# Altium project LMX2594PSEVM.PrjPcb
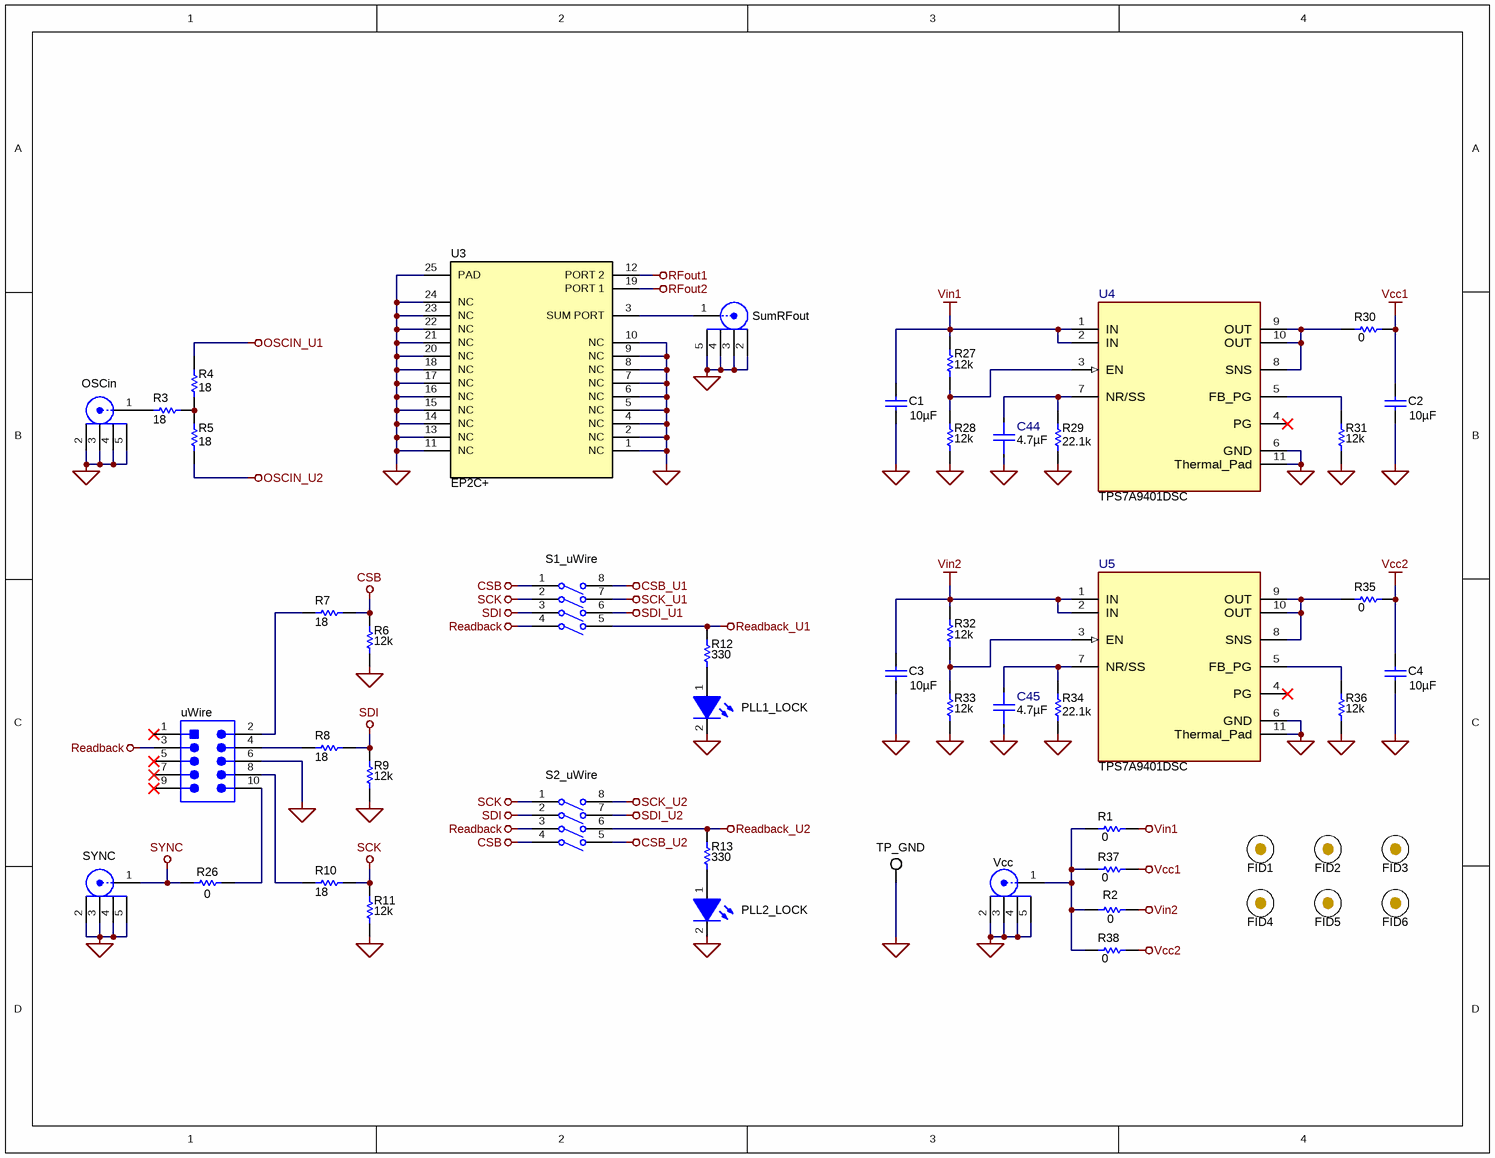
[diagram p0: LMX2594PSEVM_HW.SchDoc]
CopyrightYear: 2022; PCB_Layout: Dean Banerjee; PCB_Rev: A; PRJ_Customer: Public Release; PRJ_Engineer: Dean Banerjee; PRJ_Number: DC193; PRJ_Title: LMX2594 Phase Sync EVM; SCH_Rev: A; TechSupport: http://www.ti.com/support; TID: N/A
3 sheets, 123 parts. Net scope: global (net labels, ports and power ports of the same name join across sheets).
Board file: LMX2594PSEVM.PcbDoc
Sheets:
  LMX2594PSEVM_HW.SchDoc
  LMX2594PSEVM_SYNTH1.SchDoc
  LMX2594PSEVM_SYNTH2.SchDoc

## Sheet LMX2594PSEVM_HW.SchDoc: Power supply and control interface
size Letter; Date: Not shown in title block; ApprovedBy: Not shown in title block; CheckedBy: Not shown in title block; Author: Not shown in title block; CompanyName: Not shown in title block; DrawnBy: Dean Banerjee; Engineer: Not shown in title block; Organization: Not shown in title block; Address1: Not shown in title block; Address2: Not shown in title block; Address3: Not shown in title block; Address4: Not shown in title block; DocumentNumber: 3; Revision: Use project parameter SCH_Rev; SheetNumber: 3; SheetTotal: 4; PageSetup: Record=PageOptions¦CenterHorizontal=True¦CenterVertical=True¦PrintScale=1.00¦XCorrection=1.00¦YCorrection=1.00¦PrintKind=0¦BorderSize=5000000¦LeftOffset=0¦BottomOffset=0¦Orientation=2¦PaperLength=1000¦PaperWidth=1000¦Scale=100¦PaperSource=15¦PrintQuality=600¦MediaType=1¦DitherType=10¦PaperKind=Letter¦PrintScaleMode=1

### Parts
C1  Cap_F: 10µF  [0805]  (hidden comment: EMK212BB7106KG-T)
C2  Cap_F: 10µF  [0805]  (hidden comment: EMK212BB7106KG-T)
C3  Cap_F: 10µF  [0805]  (hidden comment: EMK212BB7106KG-T)
C4  Cap_F: 10µF  [0805]  (hidden comment: EMK212BB7106KG-T)
C44  Cap_F: 4.7µF  [FP-CGA4J1X7R1H475K125AC_0805-MFG]  (hidden comment: CGA4J1X7R1H475K125AC)
C45  Cap_F: 4.7µF  [FP-CGA4J1X7R1H475K125AC_0805-MFG]  (hidden comment: CGA4J1X7R1H475K125AC)
D1  PLL1_LOCK  [LED_LTST-C190]
D2  PLL2_LOCK  [LED_LTST-C190]
FID1  Fiducial  [Fiducial10-20]  (value not drawn)
FID2  Fiducial  [Fiducial10-20]  (value not drawn)
FID3  Fiducial  [Fiducial10-20]  (value not drawn)
FID4  Fiducial  [Fiducial10-20]  (value not drawn)
FID5  Fiducial  [Fiducial10-20]  (value not drawn)
FID6  Fiducial  [Fiducial10-20]  (value not drawn)
J3  OSCin  [Emerson_142-0701-851]
J4  SumRFout  [Johnson_142-0761-881]
J5  SYNC  [Emerson_142-0701-851]
J6  Vcc  [Emerson_142-0701-851]
R1  value 0  [0603]  (hidden comment: Resistor)
R2  value 0  [0603]  (hidden comment: Resistor)
R3  ValueDisplayed: 18  [0603]  (hidden comment: Resistor)
R4  ValueDisplayed: 18  [0603]  (hidden comment: Resistor)
R5  ValueDisplayed: 18  [0603]  (hidden comment: Resistor)
R6  value 12k  [0603]  (hidden comment: Resistor)
R7  ValueDisplayed: 18  [0603]  (hidden comment: CRCW060318R0JNEA)
R8  ValueDisplayed: 18  [0603]  (hidden comment: CRCW060318R0JNEA)
R9  value 12k  [0603]  (hidden comment: Resistor)
R10  ValueDisplayed: 18  [0603]  (hidden comment: CRCW060318R0JNEA)
R11  value 12k  [0603]  (hidden comment: Resistor)
R12  value 330  [0603]  (hidden comment: Resistor)
R13  value 330  [0603]  (hidden comment: Resistor)
R26  value 0  [0603]  (hidden comment: Resistor)
R27  value 12k  [0603]  (hidden comment: Resistor)
R28  value 12k  [0603]  (hidden comment: Resistor)
R29  ValueDisplayed: 22.1k  [0603]  (hidden comment: CRCW060322K1FKEA)
R30  value 0  [0603]  (hidden comment: Resistor)
R31  value 12k  [0603]  (hidden comment: Resistor)
R32  value 12k  [0603]  (hidden comment: Resistor)
R33  value 12k  [0603]  (hidden comment: Resistor)
R34  ValueDisplayed: 22.1k  [0603]  (hidden comment: CRCW060322K1FKEA)
R35  value 0  [0603]  (hidden comment: Resistor)
R36  value 12k  [0603]  (hidden comment: Resistor)
R37  value 0  [0603]  (hidden comment: Resistor)
R38  value 0  [0603]  (hidden comment: Resistor)
S1  S1_uWire  [SW_219-4MST]
S2  S2_uWire  [SW_219-4MST]
TP1  TP_GND  [Keystone5007]
U3  EP2C+  [DG1847]
U4  TPS7A9401DSC  [DSC0010J-MFG]
U5  TPS7A9401DSC  [DSC0010J-MFG]
uWire  Header_5x2  [FCI_52601-S10-8LF]  (value not drawn)

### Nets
CSB: R6.2 R7.2 S1.1(A1) S2.4(A4)
CSB_U1: S1.8(B1)
CSB_U2: S2.5(B4)
GND: C1.1 C2.1 C3.1 C4.1 C44.1 C45.1 D1.2(K) D2.2(K) J3.2 J3.3 J3.4 J3.5 J4.2 J4.3 J4.4 J4.5 J5.2 J5.3 J5.4 J5.5 J6.2 J6.3 J6.4 J6.5 R6.1 R9.1 R11.1 R28.1 R29.1 R31.1 R33.1 R34.1 R36.1 TP1.1 U3.1(NC) U3.2(NC) U3.4(NC) U3.5(NC) U3.6(NC) U3.7(NC) U3.8(NC) U3.9(NC) U3.10(NC) U3.11(NC) U3.13(NC) U3.14(NC) U3.15(NC) U3.16(NC) U3.17(NC) U3.18(NC) U3.20(NC) U3.21(NC) U3.22(NC) U3.23(NC) U3.24(NC) U3.25(PAD) U4.6(GND) U4.11(Thermal_Pad) U5.6(GND) U5.11(Thermal_Pad) uWire.6
OSCIN_U1: R4.2
OSCIN_U2: R5.1
Readback: S1.4(A4) S2.3(A3) uWire.3
Readback_U1: R12.2 S1.5(B4)
Readback_U2: R13.2 S2.6(B3)
RFout1: U3.12(PORT_2)
RFout2: U3.19(PORT_1)
SCK: R10.2 R11.2 S1.2(A2) S2.1(A1)
SCK_U1: S1.7(B2)
SCK_U2: S2.8(B1)
SDI: R8.1 R9.2 S1.3(A3) S2.2(A2)
SDI_U1: S1.6(B3)
SDI_U2: S2.7(B2)
SYNC: J5.1 R26.1
Vcc1: C2.2 R30.2 R37.2
Vcc2: C4.2 R35.2 R38.2
Vin1: C1.2 R1.2 R27.2 U4.1(IN) U4.2(IN)
Vin2: C3.2 R2.2 R32.2 U5.1(IN) U5.2(IN)
NetC44_2: C44.2 R29.2 U4.7(NR/SS)
NetC45_2: C45.2 R34.2 U5.7(NR/SS)
NetD1_1: D1.1(A) R12.1
NetD2_1: D2.1(A) R13.1
NetJ3_1: J3.1 R3.1
NetJ4_1: J4.1 U3.3(SUM_PORT)
NetJ6_1: J6.1 R1.1 R2.1 R37.1 R38.1
NetR3_2: R3.2 R4.1 R5.2
NetR7_1: R7.1 uWire.2
NetR8_2: R8.2 uWire.4
NetR10_1: R10.1 uWire.8
NetR26_2: R26.2 uWire.10
NetR27_1: R27.1 R28.2 U4.3(EN)
NetR30_1: R30.1 U4.8(SNS) U4.9(OUT) U4.10(OUT)
NetR31_2: R31.2 U4.5(FB_PG)
NetR32_1: R32.1 R33.2 U5.3(EN)
NetR35_1: R35.1 U5.8(SNS) U5.9(OUT) U5.10(OUT)
NetR36_2: R36.2 U5.5(FB_PG)

Not connected (* = marked no-connect by the designer): U4 4(PG)*; U5 4(PG)*; uWire 1* 5* 7* 9*

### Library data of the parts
C1-C4 = CMP-0085283-1: CAP, CERM, 10 µF, 16 V,+/- 10%, X7R, 0805; Manufacturer: Taiyo Yuden; Polarized: N; TaMax_C: 125°C; TaMin_C: -55°C; VDC_V: 16V; Value: 10uF; U/M: EA; AEC Category: Q200; SizeArea_mm2: 2.5; SizeAreaWB_mm2: 6.75; SizeX_mm: 2; SizeY_mm: 1.25; SizeZ_mm: 1.45
C44 C45 = CMP-0090082-1: Cap Ceramic 4.7uF 50V X7R 10% Pad SMD 0805 +125°C Automotive T/R; Manufacturer: TDK Corporation; TempCo: 15%; Value: 4.7µF; Tolerance_%: 0.1%; SizeZ_mm: 1.45mm; AEC Qualified: Yes; AEC Grade: Grade 1
D1 D2 = CMP-0002827-3: LED, Green, SMD; Manufacturer: Lite-On; PartNumber: LTST-C190GKT; Vf_V: 2.1V; Io_A: 20mA; Power_TotalModule: 100mW; Value1: 0.1W
FID1-FID6 = CMP-0077181-1: Fiducial mark.  There is nothing to buy or mount.
J3 J5 J6 = CMP-0055822-3: Connector, End launch SMA, 50 ohm, SMT; PartNumber: 142-0701-851; Manufacturer: Cinch Connectivity; Green_Lifecycle: Not Set; Green_REACh: Incomplete
J4 = CMP-0055835-1: Connector, End launch SMA 50 ohm, TH; PartNumber: 142-0761-881; Manufacturer: Cinch Connectivity; CNHeader: FALSE; CT: TRUE; Green_Lifecycle: Not Set; Green_REACh: Incomplete
R1 R2 R26 R30 R35 R37 R38 = CMP-0025697-4: RES, 0, 5%, 0.1 W, AEC-Q200 Grade 0, 0603; Manufacturer: Vishay-Dale; PartNumber: CRCW06030000Z0EA; VDC_V: 75V; Power_W: 100mW; Value_Code: 0000; Value2: 0.1W; EIA_Code: E24; AEC Category: Q200; AEC Qualified: Y; SizeArea_mm2: 1.28; SizeX_mm: 1.6; SizeY_mm: 0.8; SizeZ_mm: 1; TempCo: 200 ppm/C
R3-R5 = CMP-0025728-4: RES, 18, 5%, 0.1 W, AEC-Q200 Grade 0, 0603; Manufacturer: Vishay-Dale; PartNumber: CRCW060318R0JNEA; VDC_V: 75V; Power_W: 100mW; Value: 18; Value_Code: 18R0; Value2: 0.1W; EIA_Code: E24; TempCo: 200 ppm/C; SizeArea_mm2: 1.28; SizeX_mm: 1.6; SizeY_mm: 0.8; SizeZ_mm: 1; AEC Category: Q200; AEC Qualified: Y; AEC Grade: 0
R6 R9 R11 R27 R28 R31-R33 R36 = CMP-0025711-4: RES, 12 k, 5%, 0.1 W, AEC-Q200 Grade 0, 0603; Manufacturer: Vishay-Dale; PartNumber: CRCW060312K0JNEA; VDC_V: 75V; Power_W: 100mW; Value_Code: 12k0; Value2: 0.1W; EIA_Code: E24; AEC Category: Q200; AEC Grade: 0; AEC Qualified: Y; SizeArea_mm2: 1.28; SizeX_mm: 1.6; SizeY_mm: 0.8; SizeZ_mm: 1; TempCo: 200 ppm/C
R7 R8 R10 = CMP-0025728-4: RES, 18, 5%, 0.1 W, AEC-Q200 Grade 0, 0603; Manufacturer: Vishay-Dale; VDC_V: 75V; Power_W: 100mW; Value: 18; Value_Code: 18R0; Value2: 0.1W; EIA_Code: E24; AEC Category: Q200; AEC Grade: 0; AEC Qualified: Y; SizeArea_mm2: 1.28; SizeX_mm: 1.6; SizeY_mm: 0.8; SizeZ_mm: 1; TempCo: 200 ppm/C
R12 R13 = CMP-0025912-5: RES, 330, 5%, 0.1 W, 0603; Manufacturer: Yageo; PartNumber: RC0603JR-07330RL; VDC_V: 75V; Power_W: 100mW; Value_Code: 330R; Value2: 0.1W; EIA_Code: E24; AEC Category: Q200; AEC Qualified: N; SizeArea_mm2: 1.28; SizeAreaWB_mm2: 4.68; SizeX_mm: 1.6; SizeY_mm: 0.8; SizeZ_mm: 1; TempCo: 100 ppm/C
R29 R34 = CMP-0022220-4: RES, 22.1 k, 1%, 0.1 W, AEC-Q200 Grade 0, 0603; Manufacturer: Vishay-Dale; Power_W: 100mW; TempCo: 100 ppm/C; Value_Code: 22k1; Value: 22.1k; EIA_Code: E96; SizeX_mm: 1.6; SizeY_mm: 0.8; SizeZ_mm: 1; Value2: 0.1W; SizeArea_mm2: 1.28; AEC Qualified: Y; VDC_V: 75V; AEC Category: Q200; AEC Grade: 0
S1 S2 = CMP-0002291-1: Switch, SPST, Slide, Off-On, 4 Pos, 0.1A, 20V, SMD; PartNumber: 219-4MST; Manufacturer: CTS Electrocomponents; PositionCount: 4; CurrentRating_mA: 100A; SizeArea_mm2: 115.2533; SizeAreaWB_mm2: 162.3333; SizeX_mm: 9.91; SizeY_mm: 11.63; SizeZ_mm: 4.23
TP1 = CMP-0055144-2: Test Point, Compact, White, TH; Manufacturer: Keystone Electronics; CNHeader: FALSE; ContactFinish: Silver; CT: TRUE; Green_Lifecycle: Active; Green_REACh: Passed
U3 = CMP-0065468-1: Power Splitter/Combiner, 2 Way-0°, 50Ohm, 1800 to 12500 MHz; Manufacturer: Minicircuits; SizeArea_mm2: 16.0; SizeAreaWB_mm2: 25.0; SizeX_mm: 4.0; SizeZ_mm: 1.0
U4 U5 = CMP-0091022-1: 1-A, Ultra-Low Noise, Ultra-High PSRR, RF Voltage Regulator; Manufacturer: Texas Instruments; Max Supply Voltage: 5.5V; Accuracy Percentage: 1-1.5%; SizeZ_mm: 0.8mm; Output Type: AdjustableProgrammable; Min Supply Voltage: 1.7V; TJmax_C: +150°C; Dropout Voltage: 210mV; AEC Qualified: No; Standoff Height: 0mm; Output Voltage: 0.4-5.3V; Number Of Outputs: 1; Nominal Supply Current: 15-47mA
uWire = CMP-0055434-2: Header (shrouded), 100mil, 5x2, Gold, SMT; Manufacturer: FCI; PartNumber: 52601-S10-8LF; Green_Lifecycle: Active; Green_REACh: Passed

## Sheet LMX2594PSEVM_SYNTH1.SchDoc: Synthesizer 1
size Letter; Date: Not shown in title block; ApprovedBy: Not shown in title block; CheckedBy: Not shown in title block; Author: Not shown in title block; CompanyName: Not shown in title block; Engineer: Not shown in title block; Organization: Not shown in title block; Address1: Not shown in title block; Address2: Not shown in title block; Address3: Not shown in title block; Address4: Not shown in title block; DocumentNumber: 1; Revision: Use project parameter SCH_Rev; SheetNumber: 1; SheetTotal: 4; PageSetup: Record=PageOptions¦CenterHorizontal=True¦CenterVertical=True¦PrintScale=1.00¦XCorrection=1.00¦YCorrection=1.00¦PrintKind=0¦BorderSize=5000000¦LeftOffset=0¦BottomOffset=0¦Orientation=2¦PaperLength=1000¦PaperWidth=1000¦Scale=100¦PaperSource=15¦PrintQuality=600¦MediaType=1¦DitherType=10¦PaperKind=Letter¦PrintScaleMode=1
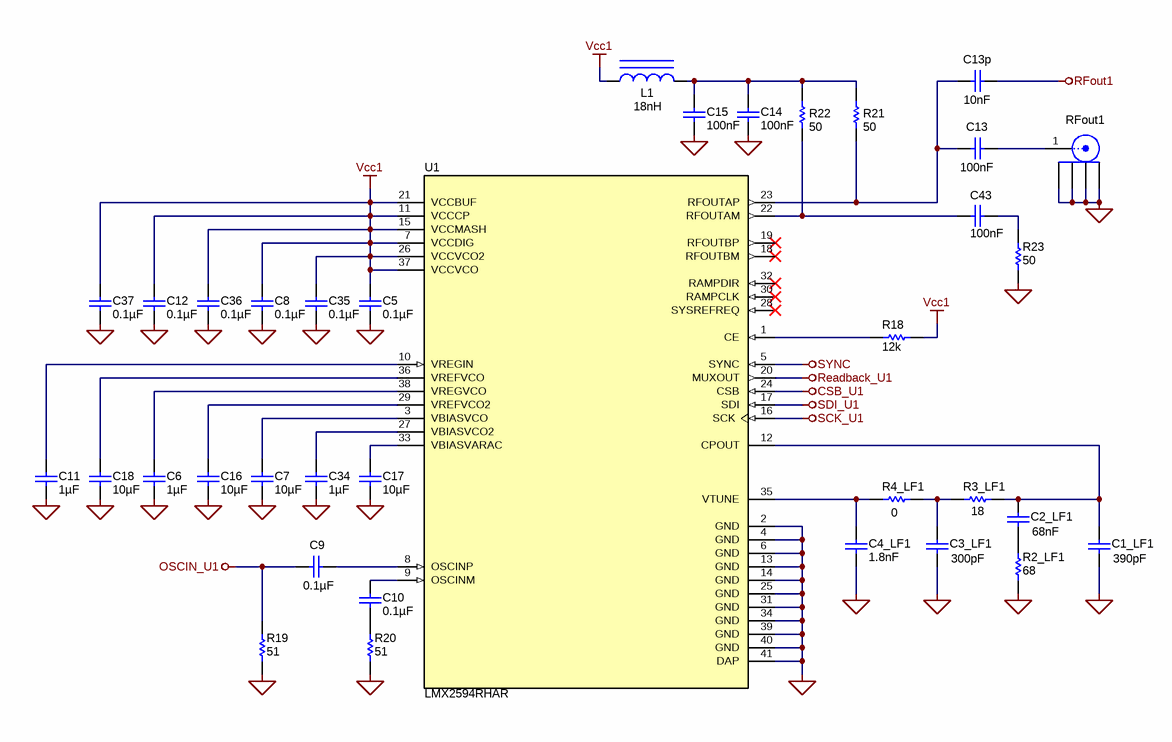
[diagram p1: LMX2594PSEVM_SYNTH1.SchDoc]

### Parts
C1_LF1  ValueDisplayed: 390pF  [0603]  (hidden comment: 06035A391JAT2A)
C2_LF1  Cap_F: 68nF  [0603]  (hidden comment: 885012206070)
C3_LF1  ValueDisplayed: 300pF  [0603]  (hidden comment: GRM1885C1H301JA01D)
C4_LF1  ValueDisplayed: 1.8nF  [0603]  (hidden comment: Capacitor)
C5  ValueDisplayed: 0.1µF  [0603]  (hidden comment: Capacitor)
C6  Cap_F: 1µF  [0603]  (hidden comment: 885012206052)
C7  ValueDisplayed: 10µF  [0603]  (hidden comment: GRM188R61A106KAALD)
C8  ValueDisplayed: 0.1µF  [0603]  (hidden comment: Capacitor)
C9  ValueDisplayed: 0.1µF  [0603]  (hidden comment: Capacitor)
C10  ValueDisplayed: 0.1µF  [0603L]  (hidden comment: Capacitor)
C11  Cap_F: 1µF  [0603]  (hidden comment: 885012206052)
C12  ValueDisplayed: 0.1µF  [0603L]  (hidden comment: Capacitor)
C13  ValueDisplayed: 100nF  [0402_065L]  (hidden comment: Capacitor)
C13p  ValueDisplayed: 10nF  [0402S]  (hidden comment: C0402C103J5RACTU)
C14  ValueDisplayed: 100nF  [0402_065L]  (hidden comment: Capacitor)
C15  ValueDisplayed: 100nF  [0402_065L]  (hidden comment: Capacitor)
C16  ValueDisplayed: 10µF  [0603]  (hidden comment: GRM188R61A106KAALD)
C17  ValueDisplayed: 10µF  [0603]  (hidden comment: GRM188R61A106KAALD)
C18  ValueDisplayed: 10µF  [0603]  (hidden comment: GRM188R61A106KAALD)
C34  Cap_F: 1µF  [0603]  (hidden comment: 885012206052)
C35  ValueDisplayed: 0.1µF  [0603L]  (hidden comment: Capacitor)
C36  ValueDisplayed: 0.1µF  [0603]  (hidden comment: Capacitor)
C37  ValueDisplayed: 0.1µF  [0603L]  (hidden comment: Capacitor)
C43  ValueDisplayed: 100nF  [0402_065L]  (hidden comment: Capacitor)
J1  RFout1  [Johnson_142-0761-881]
L1  ValueDisplayed: 18nH  [IND_LQG15H]  (hidden comment: Inductor_Iron)
R2_LF1  ValueDisplayed: 68  [0603]  (hidden comment: Resistor)
R3_LF1  ValueDisplayed: 18  [0603]  (hidden comment: Resistor)
R4_LF1  value 0  [0603]  (hidden comment: Resistor)
R18  value 12k  [0603]  (hidden comment: Resistor)
R19  ValueDisplayed: 51  [0603]  (hidden comment: Resistor)
R20  ValueDisplayed: 51  [0603]  (hidden comment: Resistor)
R21  ValueDisplayed: 50  [0402L]  (hidden comment: Resistor)
R22  ValueDisplayed: 50  [0402L]  (hidden comment: Resistor)
R23  ValueDisplayed: 50  [0402]  (hidden comment: Resistor)
U1  LMX2594RHAR  [RHA0040H]

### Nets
CSB_U1: U1.24(CSB)
GND: C1_LF1.2 C3_LF1.2 C4_LF1.2 C5.2 C6.2 C7.2 C8.1 C11.1 C12.1 C14.1 C15.1 C16.2 C17.2 C18.2 C34.1 C35.2 C36.1 C37.2 J1.2 J1.3 J1.4 J1.5 R2_LF1.2 R19.1 R20.1 R23.2 U1.2(GND) U1.4(GND) U1.6(GND) U1.13(GND) U1.14(GND) U1.25(GND) U1.31(GND) U1.34(GND) U1.39(GND) U1.40(GND) U1.41(DAP)
OSCIN_U1: C9.1 R19.2
Readback_U1: U1.20(MUXOUT)
RFout1: C13p.2
SCK_U1: U1.16(SCK)
SDI_U1: U1.17(SDI)
SYNC: U1.5(SYNC)
Vcc1: C5.1 C8.2 C12.2 C35.1 C36.2 C37.1 L1.2 R18.1 U1.7(VCCDIG) U1.11(VCCCP) U1.15(VCCMASH) U1.21(VCCBUF) U1.26(VCCVCO2) U1.37(VCCVCO)
NetC1_LF1_1: C1_LF1.1 C2_LF1.1 R3_LF1.1 U1.12(CPOUT)
NetC2_LF1_2: C2_LF1.2 R2_LF1.1
NetC3_LF1_1: C3_LF1.1 R3_LF1.2 R4_LF1.1
NetC4_LF1_1: C4_LF1.1 R4_LF1.2 U1.35(VTUNE)
NetC6_1: C6.1 U1.38(VREGVCO)
NetC7_1: C7.1 U1.3(VBIASVCO)
NetC9_2: C9.2 U1.8(OSCINP)
NetC10_1: C10.1 R20.2
NetC10_2: C10.2 U1.9(OSCINM)
NetC11_2: C11.2 U1.10(VREGIN)
NetC13_1: C13.1 C13p.1 R21.2 U1.23(RFOUTAP)
NetC13_2: C13.2 J1.1
NetC14_2: C14.2 C15.2 L1.1 R21.1 R22.2
NetC16_1: C16.1 U1.29(VREFVCO2)
NetC17_1: C17.1 U1.33(VBIASVARAC)
NetC18_1: C18.1 U1.36(VREFVCO)
NetC34_2: C34.2 U1.27(VBIASVCO2)
NetC43_1: C43.1 R23.1
NetC43_2: C43.2 R22.1 U1.22(RFOUTAM)
NetR18_2: R18.2 U1.1(CE)

Not connected (* = marked no-connect by the designer): U1 18(RFOUTBM)* 19(RFOUTBP)* 28(SYSREFREQ)* 30(RAMPCLK)* 32(RAMPDIR)*

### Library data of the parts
C1_LF1 = CMP-0006786-4: CAP, CERM, 390 pF, 50 V, +/- 5%, C0G/NP0, 0603; Manufacturer: AVX; TaMin_C: -55°C; ESR_ohm: 0.067; Polarized: N; SizeAreaWB_mm2: 4.68; Value1: 0.067 ohm; U/M: EA; Value: 390pF; TaMax_C: 125°C; SizeZ_mm: 1; SizeX_mm: 1.6; SizeY_mm: 0.8; Value2: 50V; SizeArea_mm2: 1.28; AEC Category: Q200
C2_LF1 = CMP-0750069-1: CAP, CERM, 0.068 µF, 25 V,+/- 10%, X7R, 0603; Manufacturer: Wurth Elektronik; SizeAreaWB_mm2: 4.68; U/M: EA; SizeArea_mm2: 1.28; TaMin_C: -55°C; Value: 0.068uF; SizeY_mm: 0.8; SizeX_mm: 1.6; AEC Category: Q200; VDC_V: 25V; AEC Qualified: N; SizeZ_mm: 1; TaMax_C: 125°C
C3_LF1 = CMP-0007206-4: CAP, CERM, 300 pF, 50 V, +/- 5%, C0G/NP0, 0603; Manufacturer: MuRata; TaMin_C: -55°C; Polarized: N; SizeAreaWB_mm2: 4.68; Value1: Unknown; U/M: EA; Value: 300pF; TaMax_C: 125°C; SizeZ_mm: 1; SizeX_mm: 1.6; SizeY_mm: 0.8; Value2: 50V; SizeArea_mm2: 1.28; AEC Category: Q200
C4_LF1 = CMP-0007192-4: CAP, CERM, 1800 pF, 50 V, +/- 5%, C0G/NP0, 0603; Manufacturer: MuRata; PartNumber: GRM1885C1H182JA01D; Polarized: N; TaMax_C: 125°C; TaMin_C: -55°C; VDC_V: 50V; Value: 1800pF; U/M: EA; Value1: Unknown; AEC Category: Q200; SizeArea_mm2: 1.28; SizeAreaWB_mm2: 4.68; SizeX_mm: 1.6; SizeY_mm: 0.8; SizeZ_mm: 1
C5 C8 C9 C36 = CMP-0006808-4: CAP, CERM, 0.1 uF, 16 V, +/- 5%, X7R, 0603; Manufacturer: AVX; PartNumber: 0603YC104JAT2A; ESR_ohm: 0.039; Polarized: N; TaMax_C: 125°C; TaMin_C: -55°C; VDC_V: 16V; Cap_F: 100nF; Value: 0.1uF; Value1: 0.039 ohm; U/M: EA; AEC Category: Q200; SizeArea_mm2: 1.28; SizeAreaWB_mm2: 4.68; SizeX_mm: 1.6; SizeY_mm: 0.8; SizeZ_mm: 1
C6 = CMP-0006831-4: CAP, CERM, 1 uF, 16 V, +/- 10%, X7R, 0603; Manufacturer: Wurth Elektronik; Polarized: N; TaMax_C: 125°C; TaMin_C: -55°C; VDC_V: 16V; Value: 1uF; U/M: EA; Value1: Unknown; SizeAreaWB_mm2: 4.68; SizeZ_mm: 1; SizeX_mm: 1.6; SizeY_mm: 0.8; SizeArea_mm2: 1.28; AEC Category: Q200
C7 C16-C18 = CMP-0086193-1: CAP, CERM, 10 µF, 10 V,+/- 10%, X5R, 0603; Manufacturer: MuRata; SizeArea_mm2: 1.28; SizeY_mm: 0.8; TaMax_C: 85°C; TaMin_C: -55°C; VDC_V: 10V; Polarized: N; SizeAreaWB_mm2: 4.68; SizeZ_mm: 1; SizeX_mm: 1.6; AEC Category: Q200; U/M: EA; Value: 10uF
C10 C12 C35 C37 = CMP-0006808-4: CAP, CERM, 0.1 uF, 16 V, +/- 5%, X7R, 0603; Manufacturer: AVX; PartNumber: 0603YC104JAT2A; Cap_Case: 0603; ESR_ohm: 0.039; Polarized: N; TaMax_C: 125°C; TaMin_C: -55°C; VDC_V: 16V; Cap_F: 100nF; Value: 0.1uF; Value1: 0.039 ohm; U/M: EA; AEC Category: Q200; SizeArea_mm2: 1.28; SizeAreaWB_mm2: 4.68; SizeX_mm: 1.6; SizeY_mm: 0.8; SizeZ_mm: 1
C11 = CMP-0006831-4: CAP, CERM, 1 uF, 16 V, +/- 10%, X7R, 0603; Manufacturer: Wurth Elektronik; Polarized: N; Value: 1uF; U/M: EA; Value1: Unknown; VDC_V: 16V; TaMin_C: -55°C; TaMax_C: 125°C; SizeAreaWB_mm2: 4.68; SizeZ_mm: 1; SizeX_mm: 1.6; SizeY_mm: 0.8; SizeArea_mm2: 1.28; AEC Category: Q200
C13-C15 C43 = CMP-0006210-2: CAP, CERM, 0.1 uF, 16 V, +/- 10%, X7R, 0402; PartNumber: 530L104KT16T; Manufacturer: AT Ceramics; Polarized: N; Value: 0.1uF; U/M: EA; Value1: Unknown; VDC_V: 16V; TaMin_C: -55°C; TaMax_C: 125°C; Cap_Case: 0402; SizeArea_mm2: 0.5; SizeAreaWB_mm2: 3; SizeX_mm: 1; SizeZ_mm: 0.65; AEC Category: Q200
C13p = CMP-0006236-2: CAP, CERM, 0.01 uF, 50 V, +/- 5%, X7R, 0402; Manufacturer: Kemet; Polarized: N; CompType: Capacitor; Value: 0.01uF; U/M: EA; Value1: Unknown; VDC_V: 50V; TaMin_C: -55°C; TaMax_C: 125°C; Cap_Case: 0402; SizeArea_mm2: 0.5; SizeAreaWB_mm2: 3; SizeX_mm: 1; SizeZ_mm: 0.6; AEC Category: Q200
C34 = CMP-0006831-4: CAP, CERM, 1 uF, 16 V, +/- 10%, X7R, 0603; Manufacturer: Wurth Elektronik; Polarized: N; TaMax_C: 125°C; TaMin_C: -55°C; VDC_V: 16V; Value: 1uF; U/M: EA; Value1: Unknown; AEC Category: Q200; SizeAreaWB_mm2: 4.68; SizeZ_mm: 1; SizeX_mm: 1.6; SizeY_mm: 0.8; SizeArea_mm2: 1.28
J1 = CMP-0055835-1: as J4 on sheet LMX2594PSEVM_HW
L1 = CMP-0058614-1: Inductor, Multilayer, Air Core, 18 nH, 0.3 A, 0.36 ohm, SMD; PartNumber: LQG15HS18NJ02D; Manufacturer: MuRata; Value: 18nH; Imax_A: 300mA; Irms: 0.3A @ C rise; Isat: 0.3A @ % inductance drop; DCR_ohm: 0.36; Value2: 0.3A; AEC Category: Q200; Green_Lifecycle: Active; Green_REACh: Passed; SizeArea_mm2: 0.5; SizeAreaWB_mm2: 3; SizeX_mm: 1; SizeZ_mm: 0.55
R2_LF1 = CMP-0025843-4: RES, 68, 5%, 0.1 W, AEC-Q200 Grade 0, 0603; Manufacturer: Vishay-Dale; PartNumber: CRCW060368R0JNEA; VDC_V: 75V; Power_W: 100mW; Value: 68; Value_Code: 68R0; Value2: 0.1W; TempCo: 200 ppm/C; EIA_Code: E24; SizeArea_mm2: 1.28; SizeX_mm: 1.6; SizeY_mm: 0.8; SizeZ_mm: 1; AEC Category: Q200; AEC Qualified: Y; AEC Grade: 0
R3_LF1 = CMP-0025728-4: as R3 on sheet LMX2594PSEVM_HW
R4_LF1 = CMP-0025697-4: as R1 on sheet LMX2594PSEVM_HW
R18 = CMP-0025711-4: as R6 on sheet LMX2594PSEVM_HW
R19 = CMP-0025825-4: RES, 51, 5%, 0.1 W, AEC-Q200 Grade 0, 0603; PartNumber: CRCW060351R0JNEA; Manufacturer: Vishay-Dale; Value: 51; Value_Code: 51R0; Power_W: 100mW; Value2: 0.1W; VDC_V: 75V; TempCo: 200 ppm/C; EIA_Code: E24; SizeArea_mm2: 1.28; SizeX_mm: 1.6; SizeY_mm: 0.8; SizeZ_mm: 1; AEC Category: Q200; AEC Qualified: Y; AEC Grade: 0
R20 = CMP-0025825-4: RES, 51, 5%, 0.1 W, AEC-Q200 Grade 0, 0603; PartNumber: CRCW060351R0JNEA; Manufacturer: Vishay-Dale; Value: 51; Value_Code: 51R0; Power_W: 100mW; Value2: 0.1W; VDC_V: 75V; TempCo: 200 ppm/C; EIA_Code: E24; AEC Category: Q200; AEC Qualified: Y; AEC Grade: 0; SizeArea_mm2: 1.28; SizeX_mm: 1.6; SizeY_mm: 0.8; SizeZ_mm: 1
R21-R23 = CMP-0026791-1: RES, 50, 0.1%, 0.05 W, 0402; PartNumber: FC0402E50R0BST1; Manufacturer: Vishay-Dale; Value: 50; Value_Code: 50R0; Power_W: 50mW; Value2: 0.05W; TempCo: 25 ppm/C; U/M: EA; SizeArea_mm2: 0.5; SizeX_mm: 1; SizeZ_mm: 0.6; AEC Category: Q200; AEC Qualified: N
U1 = CMP-0013786-6: 15 GHz Wideband PLLatinum(TM)RF Synthesizer with Phase Synchronization and JESD204B support, RHA0040H (VQFN-40); Alternate PartNumber: LMX2594RHAT; Manufacturer: Texas Instruments; CompType: IC; U/M: EA; SizeX_mm: 6; SizeZ_mm: 1; SizeArea_mm2: 36; SizeAreaWB_mm2: 64

## Sheet LMX2594PSEVM_SYNTH2.SchDoc: Synthesizer 2
size Letter; Date: Not shown in title block; ApprovedBy: Not shown in title block; CheckedBy: Not shown in title block; Author: Not shown in title block; CompanyName: Not shown in title block; DrawnBy: Dean Banerjee; Engineer: Not shown in title block; Organization: Not shown in title block; Address1: Not shown in title block; Address2: Not shown in title block; Address3: Not shown in title block; Address4: Not shown in title block; DocumentNumber: 2; Revision: Use project parameter SCH_Rev; SheetNumber: 2; SheetTotal: 4; PageSetup: Record=PageOptions¦CenterHorizontal=True¦CenterVertical=True¦PrintScale=1.00¦XCorrection=1.00¦YCorrection=1.00¦PrintKind=0¦BorderSize=5000000¦LeftOffset=0¦BottomOffset=0¦Orientation=2¦PaperLength=1000¦PaperWidth=1000¦Scale=100¦PaperSource=15¦PrintQuality=600¦MediaType=1¦DitherType=10¦PaperKind=Letter¦PrintScaleMode=1
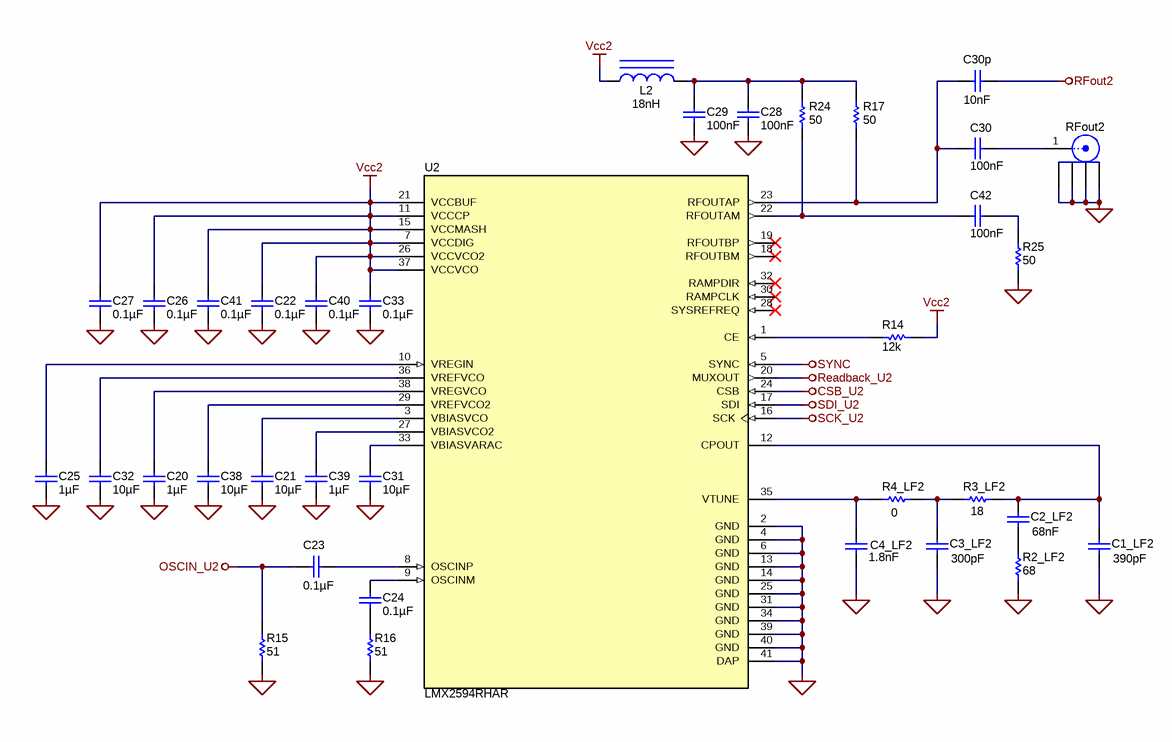
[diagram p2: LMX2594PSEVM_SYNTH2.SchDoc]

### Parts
C1_LF2  ValueDisplayed: 390pF  [0603]  (hidden comment: 06035A391JAT2A)
C2_LF2  Cap_F: 68nF  [0603]  (hidden comment: 885012206070)
C3_LF2  ValueDisplayed: 300pF  [0603]  (hidden comment: GRM1885C1H301JA01D)
C4_LF2  ValueDisplayed: 1.8nF  [0603]  (hidden comment: Capacitor)
C20  Cap_F: 1µF  [0603]  (hidden comment: 885012206052)
C21  ValueDisplayed: 10µF  [0603]  (hidden comment: GRM188R61A106KAALD)
C22  ValueDisplayed: 0.1µF  [0603]  (hidden comment: Capacitor)
C23  ValueDisplayed: 0.1µF  [0603]  (hidden comment: Capacitor)
C24  ValueDisplayed: 0.1µF  [0603L]  (hidden comment: Capacitor)
C25  Cap_F: 1µF  [0603]  (hidden comment: 885012206052)
C26  ValueDisplayed: 0.1µF  [0603]  (hidden comment: Capacitor)
C27  ValueDisplayed: 0.1µF  [0603L]  (hidden comment: Capacitor)
C28  ValueDisplayed: 100nF  [0402_065L]  (hidden comment: Capacitor)
C29  ValueDisplayed: 100nF  [0402_065L]  (hidden comment: Capacitor)
C30  ValueDisplayed: 100nF  [0402_065L]  (hidden comment: Capacitor)
C30p  ValueDisplayed: 10nF  [0402S]  (hidden comment: C0402C103J5RACTU)
C31  ValueDisplayed: 10µF  [0603]  (hidden comment: GRM188R61A106KAALD)
C32  ValueDisplayed: 10µF  [0603]  (hidden comment: GRM188R61A106KAALD)
C33  ValueDisplayed: 0.1µF  [0603]  (hidden comment: Capacitor)
C38  ValueDisplayed: 10µF  [0603]  (hidden comment: GRM188R61A106KAALD)
C39  Cap_F: 1µF  [0603]  (hidden comment: 885012206052)
C40  ValueDisplayed: 0.1µF  [0603L]  (hidden comment: Capacitor)
C41  ValueDisplayed: 0.1µF  [0603]  (hidden comment: Capacitor)
C42  ValueDisplayed: 100nF  [0402_065L]  (hidden comment: Capacitor)
J2  RFout2  [Johnson_142-0761-881]
L2  ValueDisplayed: 18nH  [IND_LQG15H]  (hidden comment: Inductor_Iron)
R2_LF2  ValueDisplayed: 68  [0603]  (hidden comment: Resistor)
R3_LF2  ValueDisplayed: 18  [0603]  (hidden comment: Resistor)
R4_LF2  value 0  [0603]  (hidden comment: Resistor)
R14  value 12k  [0603]  (hidden comment: Resistor)
R15  ValueDisplayed: 51  [0603]  (hidden comment: Resistor)
R16  ValueDisplayed: 51  [0603]  (hidden comment: Resistor)
R17  ValueDisplayed: 50  [0402L]  (hidden comment: Resistor)
R24  ValueDisplayed: 50  [0402L]  (hidden comment: Resistor)
R25  ValueDisplayed: 50  [0402]  (hidden comment: Resistor)
U2  LMX2594RHAR  [RHA0040H]

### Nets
CSB_U2: U2.24(CSB)
GND: C1_LF2.2 C3_LF2.2 C4_LF2.2 C20.2 C21.1 C22.1 C25.1 C26.1 C27.2 C28.1 C29.1 C31.1 C32.1 C33.2 C38.2 C39.1 C40.2 C41.1 J2.2 J2.3 J2.4 J2.5 R2_LF2.2 R15.1 R16.1 R25.2 U2.2(GND) U2.4(GND) U2.6(GND) U2.13(GND) U2.14(GND) U2.25(GND) U2.31(GND) U2.34(GND) U2.39(GND) U2.40(GND) U2.41(DAP)
OSCIN_U2: C23.1 R15.2
Readback_U2: U2.20(MUXOUT)
RFout2: C30p.1
SCK_U2: U2.16(SCK)
SDI_U2: U2.17(SDI)
SYNC: U2.5(SYNC)
Vcc2: C22.2 C26.2 C27.1 C33.1 C40.1 C41.2 L2.2 R14.1 U2.7(VCCDIG) U2.11(VCCCP) U2.15(VCCMASH) U2.21(VCCBUF) U2.26(VCCVCO2) U2.37(VCCVCO)
NetC1_LF2_1: C1_LF2.1 C2_LF2.1 R3_LF2.1 U2.12(CPOUT)
NetC2_LF2_2: C2_LF2.2 R2_LF2.1
NetC3_LF2_1: C3_LF2.1 R3_LF2.2 R4_LF2.1
NetC4_LF2_1: C4_LF2.1 R4_LF2.2 U2.35(VTUNE)
NetC20_1: C20.1 U2.38(VREGVCO)
NetC21_2: C21.2 U2.3(VBIASVCO)
NetC23_2: C23.2 U2.8(OSCINP)
NetC24_1: C24.1 R16.2
NetC24_2: C24.2 U2.9(OSCINM)
NetC25_2: C25.2 U2.10(VREGIN)
NetC28_2: C28.2 C29.2 L2.1 R17.1 R24.2
NetC30_1: C30.1 J2.1
NetC30_2: C30.2 C30p.2 R17.2 U2.23(RFOUTAP)
NetC31_2: C31.2 U2.33(VBIASVARAC)
NetC32_2: C32.2 U2.36(VREFVCO)
NetC38_1: C38.1 U2.29(VREFVCO2)
NetC39_2: C39.2 U2.27(VBIASVCO2)
NetC42_1: C42.1 R25.1
NetC42_2: C42.2 R24.1 U2.22(RFOUTAM)
NetR14_2: R14.2 U2.1(CE)

Not connected (* = marked no-connect by the designer): U2 18(RFOUTBM)* 19(RFOUTBP)* 28(SYSREFREQ)* 30(RAMPCLK)* 32(RAMPDIR)*

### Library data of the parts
C1_LF2 = CMP-0006786-4: as C1_LF1 on sheet LMX2594PSEVM_SYNTH1
C2_LF2 = CMP-0750069-1: as C2_LF1 on sheet LMX2594PSEVM_SYNTH1
C3_LF2 = CMP-0007206-4: as C3_LF1 on sheet LMX2594PSEVM_SYNTH1
C4_LF2 = CMP-0007192-4: as C4_LF1 on sheet LMX2594PSEVM_SYNTH1
C20 = CMP-0006831-4: as C6 on sheet LMX2594PSEVM_SYNTH1
C21 C31 C32 C38 = CMP-0086193-1: as C7 on sheet LMX2594PSEVM_SYNTH1
C22 C23 C26 C33 C41 = CMP-0006808-4: as C5 on sheet LMX2594PSEVM_SYNTH1
C24 C27 C40 = CMP-0006808-4: as C10 on sheet LMX2594PSEVM_SYNTH1
C25 C39 = CMP-0006831-4: as C11 on sheet LMX2594PSEVM_SYNTH1
C28-C30 C42 = CMP-0006210-2: as C13 on sheet LMX2594PSEVM_SYNTH1
C30p = CMP-0006236-2: as C13p on sheet LMX2594PSEVM_SYNTH1
J2 = CMP-0055835-1: as J4 on sheet LMX2594PSEVM_HW
L2 = CMP-0058614-1: as L1 on sheet LMX2594PSEVM_SYNTH1
R2_LF2 = CMP-0025843-4: as R2_LF1 on sheet LMX2594PSEVM_SYNTH1
R3_LF2 = CMP-0025728-4: as R3 on sheet LMX2594PSEVM_HW
R4_LF2 = CMP-0025697-4: as R1 on sheet LMX2594PSEVM_HW
R14 = CMP-0025711-4: as R6 on sheet LMX2594PSEVM_HW
R15 = CMP-0025825-4: as R19 on sheet LMX2594PSEVM_SYNTH1
R16 = CMP-0025825-4: as R20 on sheet LMX2594PSEVM_SYNTH1
R17 R24 R25 = CMP-0026791-1: as R21 on sheet LMX2594PSEVM_SYNTH1
U2 = CMP-0013786-6: as U1 on sheet LMX2594PSEVM_SYNTH1

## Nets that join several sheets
CSB_U1: LMX2594PSEVM_HW (S1.8), LMX2594PSEVM_SYNTH1 (U1.24)
CSB_U2: LMX2594PSEVM_HW (S2.5), LMX2594PSEVM_SYNTH2 (U2.24)
GND: LMX2594PSEVM_HW (61 pins), LMX2594PSEVM_SYNTH1 (37 pins), LMX2594PSEVM_SYNTH2 (37 pins)
OSCIN_U1: LMX2594PSEVM_HW (R4.2), LMX2594PSEVM_SYNTH1 (C9.1 R19.2)
OSCIN_U2: LMX2594PSEVM_HW (R5.1), LMX2594PSEVM_SYNTH2 (C23.1 R15.2)
Readback_U1: LMX2594PSEVM_HW (R12.2 S1.5), LMX2594PSEVM_SYNTH1 (U1.20)
Readback_U2: LMX2594PSEVM_HW (R13.2 S2.6), LMX2594PSEVM_SYNTH2 (U2.20)
RFout1: LMX2594PSEVM_HW (U3.12), LMX2594PSEVM_SYNTH1 (C13p.2)
RFout2: LMX2594PSEVM_HW (U3.19), LMX2594PSEVM_SYNTH2 (C30p.1)
SCK_U1: LMX2594PSEVM_HW (S1.7), LMX2594PSEVM_SYNTH1 (U1.16)
SCK_U2: LMX2594PSEVM_HW (S2.8), LMX2594PSEVM_SYNTH2 (U2.16)
SDI_U1: LMX2594PSEVM_HW (S1.6), LMX2594PSEVM_SYNTH1 (U1.17)
SDI_U2: LMX2594PSEVM_HW (S2.7), LMX2594PSEVM_SYNTH2 (U2.17)
SYNC: LMX2594PSEVM_HW (J5.1 R26.1), LMX2594PSEVM_SYNTH1 (U1.5), LMX2594PSEVM_SYNTH2 (U2.5)
Vcc1: LMX2594PSEVM_HW (C2.2 R30.2 R37.2), LMX2594PSEVM_SYNTH1 (14 pins)
Vcc2: LMX2594PSEVM_HW (C4.2 R35.2 R38.2), LMX2594PSEVM_SYNTH2 (14 pins)

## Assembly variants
001: not fitted C3_LF1 C3_LF2 C13p C30p FID1 FID2 FID3 FID4 FID5 FID6 R37 R38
